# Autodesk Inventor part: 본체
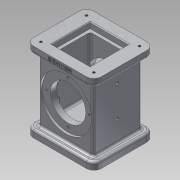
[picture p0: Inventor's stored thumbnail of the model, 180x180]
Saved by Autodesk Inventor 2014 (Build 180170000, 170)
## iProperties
Created: 2017-08
Part Number: 본체
Material: 알루미늄 6061
Document SubType Name: 모델링
Designer: user
Density: 2.71 g/cm^3
Appearance: 알루미늄 - 평지
Mass: 883.549 g
Surface Area: 674.681 cm^2
Volume: 326.033 cm^3
Author: user
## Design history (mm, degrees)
sketch "스케치2"
  geometry: L1 (46, -41)-(-46, -41); L2 (-46, -41)-(-46, 41); L3 (-46, 41)-(46, 41); L4 (46, 41)-(46, -41); L5 (46, -41)-(-46, 41); L6 (-46, -41)-(46, 41); 1 further point
  constraints: 12 end point, 2 midpoint, 2 parallel, 1 horizontal, 1 perpendicular
  dimensions: "d0" = 92 distance of L1.start L1.end; "d1" = 82 distance of L3.end L1.start
extrude "돌출1" join sketch "스케치2" distance "d2" = 10; taper "d3" = 0 deg
sketch "스케치3"
  geometry: L1 (-37, -33)-(37, -33); L2 (37, -33)-(37, 33); L3 (37, 33)-(-37, 33); L4 (-37, 33)-(-37, -33); L5 (-37, -33)-(37, 33); L6 (37, -33)-(-37, 33); 1 further point
  constraints: 12 end point, 2 midpoint, 2 parallel, 1 horizontal, 1 perpendicular
  dimensions: "d4" = 74 distance of L2.end L3.end; "d5" = 66 distance of L1.end L2.end
extrude "돌출2" join sketch "스케치3" distance "d6" = 88; taper "d7" = 0 deg
sketch "스케치4"
  geometry: L1 (-46, -41)-(46, -41); L2 (46, -41)-(46, 41); L3 (46, 41)-(-46, 41); L4 (-46, 41)-(-46, -41); L5 (-46, -41)-(46, 41); L6 (46, -41)-(-46, 41); 1 further point
  constraints: 12 end point, 2 midpoint, 2 parallel, 1 horizontal, 1 perpendicular
extrude "돌출3" join sketch "스케치4" distance "d8" = 10; taper "d9" = 0 deg
sketch "스케치5"
  geometry: L1 (83, -10)-(-9, -10) reference; C1 r 35 at (37, 44); 1 further point
  constraints: 1 centre point
  dimensions: "d10" = 54 distance from line of L1 C1.centre; "d11" = 70 diameter of C1
extrude "돌출4" cut sketch "스케치5" distance "d12" = 3; taper "d13" = 0 deg
sketch "스케치6"
  geometry: C1 r 35 at (0, 0) reference; C2 r 24 at (0, 0); 1 further point
  constraints: 1 centre point, 1 coincident
  dimensions: "d14" = 48 diameter of C2
extrude "돌출5" cut sketch "스케치6" distance "d15" = 8; taper "d16" = 0 deg
sketch "스케치7"
  geometry: L1 (-26, -26)-(26, -26); L2 (26, -26)-(26, 26); L3 (26, 26)-(-26, 26); L4 (-26, 26)-(-26, -26); L5 (-26, -26)-(26, 26); L6 (26, -26)-(-26, 26); 1 further point
  constraints: 12 end point, 2 midpoint, 2 parallel, 1 horizontal, 1 perpendicular
  dimensions: "d17" = 52 distance of L3.end L2.end; "d18" = 52 distance of L1.end L2.end
extrude "돌출6" cut sketch "스케치7" distance "d19" = 8; taper "d20" = 0 deg
sketch "스케치8"
  geometry: L1 (-22, -22)-(22, -22); L2 (22, -22)-(22, 22); L3 (22, 22)-(-22, 22); L4 (-22, 22)-(-22, -22); L5 (-22, -22)-(22, 22); L6 (22, -22)-(-22, 22); 1 further point
  constraints: 12 end point, 2 midpoint, 2 parallel, 1 horizontal, 1 perpendicular
  dimensions: "d21" = 44 distance of L3.end L2.end; "d22" = 44 distance of L1.end L2.end
extrude "돌출7" cut sketch "스케치8" distance "d23" = 74; taper "d24" = 0 deg
sketch "스케치9"
  geometry: L1 (-24, -24)-(24, -24); L2 (24, -24)-(24, 24); L3 (24, 24)-(-24, 24); L4 (-24, 24)-(-24, -24); L5 (-24, -24)-(24, 24); L6 (24, -24)-(-24, 24); 1 further point
  constraints: 12 end point, 2 midpoint, 2 parallel, 1 horizontal, 1 perpendicular
  dimensions: "d25" = 48 distance of L1.end L2.end; "d26" = 48 distance of L2.end L3.end
extrude "돌출8" cut sketch "스케치9" distance "d27" = 16; taper "d28" = 0 deg
sketch "스케치10" dims "d29" = 58
  geometry: C1 r 35 at (0, 0) reference; 3 further points
  constraints: 1 coincident, 1 vertical alignment, 2 other
hole "구멍1" sketch "스케치10" at (0, 29) diameter "d30" = 3.242; stored, may be unused: countersink angle "d34" = 90 deg, drill point angle "d36" = 118 deg; dims "d31" = 4, "d32" = 4, "d33" = 2, "d35" = 6
sketch "스케치11"
  geometry: L1 (46, 41)-(-46, 41) reference; L2 (-46, 41)-(-46, -41) reference; 2 further points
  dimensions: "d40" = 10 distance from line of L1 point (-36, 31); "d41" = 10 distance from line of point (-36, 31) L2
hole "구멍2" sketch "스케치11" at (-36, 31) diameter "d42" = 3.242; stored, may be unused: countersink angle "d46" = 90 deg, drill point angle "d48" = 118 deg; dims "d43" = 4, "d44" = 4, "d45" = 2, "d47" = 6
node "작업 평면1"
fillet "모깎기1" dims "d50" = 10
sketch "스케치12"
  geometry: L1 (10, 64)-(10, 2) reference; 3 further points
  dimensions: "d51" = 38 distance from line of L1 point (-28, 33); "d52" = 42 distance of point (-28, 33) point (-70, 33)
hole "구멍3" sketch "스케치12" at (-28, 33), (-70, 33) diameter "d53" = 4.134; stored, may be unused: countersink angle "d57" = 90 deg, drill point angle "d59" = 118 deg; dims "d54" = 4, "d55" = 4, "d56" = 2, "d58" = 6
fillet "모깎기2" dims "d60" = 3
fillet "모깎기3" dims "d61" = 3
fillet "모깎기4" dims "d62" = 3
fillet "모깎기5" dims "d63" = 3
chamfer "모따기1" distance "d64" = 1; stored, may be unused: second distance "d65" = 2, angle "d66" = 45 deg
sketch "스케치13"
  geometry: L1 (0, 0)-(72, 0) reference; L2 (19.446, -1.598)-(52.554, -1.598); L3 (52.554, -1.598)-(52.554, -6.402); L4 (52.554, -6.402)-(19.446, -6.402); L5 (19.446, -6.402)-(19.446, -1.598); L6 (36, -1.598)-(36, -6.402); L7 (19.446, -4)-(36, -4); L8 (-10, 0)-(-10, -7) reference; 1 further point
  constraints: 4 end point, 4 midpoint, 2 other
  dimensions: "d67" = 4 distance between parallel lines of L1 L7; "d68" = 46 distance between parallel lines of L6 L8
feature "엠보싱1" sketch "스케치13" dims "d69" = 0.5, "d70" = 0, "GapSize" = 0.5 (= Thickness), "SeamGap" = 0.01, "Thickness" = 0.5, "BendRadius" = 0.5 (= Thickness), "MinimumRemnant" = 1 (= 2 x Thickness), "BendReliefDepth" = 0.25 (= 0.5 x Thickness), "BendReliefWidth" = 0.5 (= Thickness), "CornerReliefSize" = 2 (= 4 x Thickness), "JacobiRadiusSize" = 0.5 (= BendRadius), "TransitionRadius" = 0.5 (= BendRadius)
node "솔리드1"
mirror "대칭1"
pattern_circular "원형 패턴1" dims angle "d38" = 360 deg
mirror "대칭2"
mirror "대칭3"
mirror "대칭4"
mirror "대칭5"
other parameters: "d49" = -54
